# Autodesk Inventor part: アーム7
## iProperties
Created: 2008-02
Part Number: アーム7
Document SubType Name: Modeling
Designer: y-shimazaki
Density: 1 g/cm^3
Author: y-shimazaki
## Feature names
1. 押し出し1 [Extrusion]
2. 押し出し2 [Extrusion]
3. 押し出し3 [Extrusion]
4. 押し出し4 [Extrusion]
